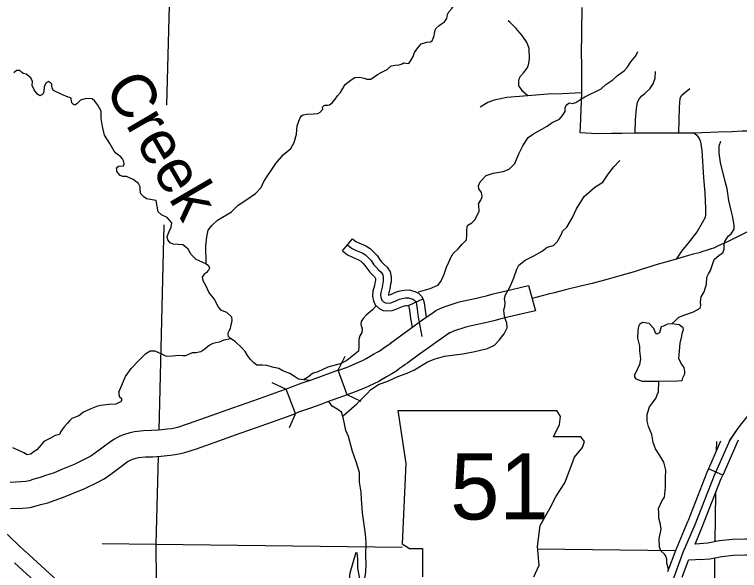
# Model space of a CAD drawing. Extents: x 813775 to 1157140, y 1757555 to 1979907.
# Drawn here: x 951173 to 965049, y 1822306 to 1832939 of the extents above; entities that cross this region are included whole.
import ezdxf

# ---------------------------------------------------------------- set-up
doc = ezdxf.new("R2010")
doc.units = 0
for name, color, linetype in [('Level 10', 7, 'Continuous'), ('Level 21', 7, 'Continuous'), ('Level 31', 7, 'Continuous'), ('Level 32', 7, 'Continuous'), ('Level 35', 7, 'Continuous'), ('Level 37', 7, 'Continuous'), ('Level 45', 7, 'Continuous'), ('Level 5', 7, 'Continuous')]:
    doc.layers.add(name, color=color, linetype=linetype)

msp = doc.modelspace()

# ---------------------------------------------------------------- linework, layer by layer
at = {"layer": 'Level 10'}
msp.add_line((958386, 1826665), (958378, 1826659), dxfattribs=at)
for points in [[(965811, 1829193), (965710, 1829119), (965609, 1829037), (965530, 1828986), (965404, 1828901), (965305, 1828839), (965153, 1828760), (964848, 1828606)], [(964848, 1828606), (964700, 1828538), (964630, 1828506), (964569, 1828479), (964485, 1828450), (964413, 1828426), (964348, 1828405), (964276, 1828380), (964163, 1828353), (964073, 1828328)], [(964073, 1828328), (963835, 1828263), (963727, 1828227), (963613, 1828194), (963517, 1828168), (963412, 1828138), (963315, 1828108), (963187, 1828068)], [(963187, 1828068), (963034, 1828021), (962806, 1827951), (962538, 1827878), (962232, 1827796)], [(962232, 1827796), (962009, 1827743), (961722, 1827676), (961499, 1827617), (961370, 1827584), (961080, 1827505)], [(960041, 1827522), (960223, 1827566), (960336, 1827598), (960499, 1827635), (960691, 1827682), (961011, 1827757), (961143, 1827275)], [(959237, 1827276), (959322, 1827316), (959398, 1827347), (959493, 1827381), (959587, 1827410), (959664, 1827435), (959743, 1827458), (960046, 1827523)], [(958378, 1826659), (958628, 1826845), (958824, 1826985), (958964, 1827087), (959055, 1827151), (959160, 1827221), (959237, 1827276)], [(961143, 1827275), (960809, 1827196), (960614, 1827148), (960459, 1827113), (960350, 1827082), (960158, 1827036)], [(960152, 1827035), (959865, 1826972), (959811, 1826957), (959737, 1826933), (959650, 1826906), (959575, 1826880), (959523, 1826859), (959472, 1826834)], [(959511, 1826857), (959445, 1826810), (959337, 1826738), (959254, 1826680), (959117, 1826580), (958922, 1826441), (958675, 1826257)], [(957416, 1826151), (957559, 1826204), (957686, 1826257), (957832, 1826323), (957902, 1826360), (957981, 1826405), (958047, 1826444), (958137, 1826495), (958201, 1826535), (958248, 1826572), (958335, 1826631), (958386, 1826665)], [(957371, 1826135), (957401, 1826146), (957559, 1826204), (957686, 1826257), (957832, 1826323), (957882, 1826349)], [(958666, 1826251), (958616, 1826217), (958542, 1826167), (958490, 1826126), (958395, 1826066), (958296, 1826010), (958231, 1825972), (958143, 1825921), (958051, 1825873), (957885, 1825799), (957742, 1825739), (957588, 1825682)], [(957371, 1826135), (957214, 1826079), (957042, 1826017), (956852, 1825945), (956675, 1825886), (956434, 1825800), (956372, 1825777)], [(957539, 1825664), (957371, 1826135)], [(958218, 1825965), (958143, 1825921), (958051, 1825873), (957885, 1825799), (957742, 1825739), (957539, 1825664)], [(956372, 1825777), (956227, 1825721), (955944, 1825620), (955510, 1825469), (955326, 1825404), (954844, 1825232), (954499, 1825108), (954292, 1825043), (954240, 1825029), (954176, 1825017), (954100, 1825009), (953933, 1824990), (953797, 1824982), (953645, 1824978), (953470, 1824959), (953379, 1824941), (953257, 1824903), (953192, 1824874), (953074, 1824814)], [(956550, 1825309), (956372, 1825777)], [(957539, 1825664), (957383, 1825609), (957215, 1825548), (957020, 1825474), (956838, 1825413), (956606, 1825331), (956549, 1825309)], [(953330, 1824383), (953406, 1824422), (953434, 1824434), (953504, 1824456), (953547, 1824465), (953679, 1824479), (953818, 1824483), (953974, 1824492), (954156, 1824512), (954250, 1824522), (954350, 1824541), (954432, 1824562), (954659, 1824634), (955013, 1824761), (955494, 1824933), (955675, 1824997), (956110, 1825148), (956400, 1825252), (956549, 1825309)], [(953074, 1824814), (952994, 1824756), (952872, 1824665), (952725, 1824555), (952633, 1824490)], [(952633, 1824490), (952532, 1824439), (952314, 1824331), (952092, 1824241), (951935, 1824175), (951767, 1824120), (951663, 1824082), (951542, 1824050), (951451, 1824023), (951391, 1824007), (951297, 1823999), (951091, 1823991)], [(952891, 1824061), (953018, 1824150), (953172, 1824264), (953330, 1824383)], [(951096, 1823491), (951329, 1823500), (951476, 1823513), (951586, 1823541), (951676, 1823569), (951812, 1823603), (951932, 1823648), (952110, 1823707), (952282, 1823778), (952519, 1823875), (952756, 1823992), (952891, 1824061)]]:
    msp.add_lwpolyline(points, dxfattribs=at)
at = {"layer": 'Level 21'}
for p, q in [((958510, 1825367), (958662, 1824352)), ((961623, 1825249), (961553, 1825366)), ((961606, 1825097), (961623, 1825249)), ((961488, 1824860), (961606, 1825097)), ((962012, 1824860), (961488, 1824860)), ((962080, 1824775), (962012, 1824860)), ((962046, 1824657), (962080, 1824775)), ((961894, 1824471), (962046, 1824657)), ((961809, 1824251), (961894, 1824471)), ((958662, 1824352), (958595, 1822813)), ((961707, 1823980), (961809, 1824251)), ((961538, 1823726), (961707, 1823980)), ((961420, 1823489), (961538, 1823726)), ((961234, 1823168), (961420, 1823489)), ((961183, 1822762), (961234, 1823168)), ((958595, 1822813), (958730, 1822728)), ((958730, 1822728), (958984, 1822728)), ((958984, 1822728), (958984, 1822187)), ((961217, 1822407), (961183, 1822762)), ((961115, 1822187), (961217, 1822407))]:
    msp.add_line(p, q, dxfattribs=at)
msp.add_lwpolyline([(958510, 1825367), (961553, 1825366)], dxfattribs=at)
at = {"layer": 'Level 31'}
for p, q in [((964730, 1824131), (964455, 1824252)), ((964343, 1823155), (964343, 1823155))]:
    msp.add_line(p, q, dxfattribs=at)
for points in [[(962033, 1833075), (962021, 1832151), (962022, 1832019)], [(962022, 1832019), (962026, 1831438), (962009, 1830963)], [(962026, 1831438), (961904, 1831434), (961656, 1831423), (961382, 1831416), (961001, 1831383), (960594, 1831354), (960355, 1831303), (960230, 1831258), (960088, 1831165)], [(962009, 1830963), (962008, 1830938), (961995, 1830680), (962332, 1830663), (962600, 1830667), (962797, 1830670)], [(963853, 1830676), (963889, 1830676), (964172, 1830678), (964644, 1830696), (964908, 1830701)], [(964908, 1830701), (964913, 1830701), (965103, 1830712), (965587, 1830712), (965854, 1830716), (965964, 1830717)], [(962797, 1830670), (963053, 1830674), (963853, 1830676)], [(964172, 1830678), (964223, 1830638), (964279, 1830570), (964305, 1830501), (964327, 1830341), (964363, 1829818), (964387, 1829531), (964401, 1829229), (964401, 1829113), (964392, 1829058), (964332, 1828953), (964241, 1828789), (964088, 1828589), (963941, 1828412), (963835, 1828263)], [(965088, 1825118), (965016, 1825026), (964852, 1824786)], [(964688, 1824779), (964455, 1824252)], [(965026, 1824801), (964730, 1824131)], [(964455, 1824252), (964424, 1824181), (964064, 1823265)], [(964343, 1823155), (964701, 1824065), (964730, 1824131)], [(950610, 1823396), (950746, 1823267), (950977, 1823054), (951365, 1822681), (951374, 1822673)], [(964064, 1823265), (964054, 1823238), (963828, 1822704), (963670, 1822282)], [(964198, 1822808), (964331, 1823125), (964343, 1823155)], [(965321, 1822908), (965162, 1822905), (964917, 1822902), (964660, 1822871), (964443, 1822826), (964198, 1822808)], [(951374, 1822673), (951604, 1822465), (951992, 1822113), (952159, 1821982)], [(963951, 1822177), (964073, 1822502)], [(964286, 1822514), (964209, 1822508), (964073, 1822502)], [(964286, 1822514), (964484, 1822528), (964708, 1822575), (964937, 1822602), (965167, 1822605), (965327, 1822608)], [(951973, 1821746), (951799, 1821883), (951402, 1822243), (951173, 1822450)]]:
    msp.add_lwpolyline(points, dxfattribs=at)
at = {"layer": 'Level 32'}
for points in [[(963053, 1830674), (963060, 1830923), (963077, 1831143), (963097, 1831263), (963135, 1831332), (963177, 1831383), (963236, 1831430), (963271, 1831459), (963333, 1831518), (963395, 1831614), (963433, 1831723), (963442, 1831847)], [(963889, 1830676), (963900, 1831163), (963916, 1831341), (963947, 1831396), (963998, 1831443), (964098, 1831523)]]:
    msp.add_lwpolyline(points, dxfattribs=at)
at = {"layer": 'Level 35'}
for points in [[(959200, 1832508), (959216, 1832607), (959226, 1832639), (959245, 1832678), (959303, 1832727), (959346, 1832762), (959406, 1832800), (959449, 1832860), (959463, 1832939), (959485, 1832993), (959542, 1833056), (959604, 1833148), (959634, 1833213), (959691, 1833260), (959762, 1833292), (959797, 1833314), (959849, 1833371), (959903, 1833456), (959985, 1833608), (960009, 1833679), (960050, 1833738), (960126, 1833842), (960178, 1833923), (960218, 1833986)], [(956584, 1830807), (956632, 1830947), (956665, 1831001), (956697, 1831023), (956768, 1831034), (956898, 1831037), (956977, 1831047), (957023, 1831072), (957072, 1831129), (957070, 1831164), (957102, 1831200), (957121, 1831208), (957173, 1831205), (957203, 1831211), (957254, 1831249), (957309, 1831317), (957355, 1831382), (957415, 1831447), (957456, 1831523), (957502, 1831600), (957619, 1831687), (957689, 1831733), (957776, 1831738), (957863, 1831719), (957915, 1831700), (957996, 1831700), (958056, 1831744), (958119, 1831793), (958192, 1831828), (958306, 1831888), (958385, 1831956), (958461, 1831972), (958534, 1831975), (958594, 1831997), (958616, 1832016), (958660, 1832008), (958719, 1832005), (958757, 1832059), (958804, 1832138), (958831, 1832212), (958891, 1832301), (958956, 1832375), (959064, 1832413), (959132, 1832418), (959170, 1832435), (959189, 1832484), (959200, 1832508)], [(960823, 1830272), (960902, 1830429), (961005, 1830584), (961108, 1830658), (961367, 1830805), (961462, 1830873), (961606, 1830935), (961660, 1831006), (961712, 1831082), (961714, 1831153), (961731, 1831207), (961782, 1831245), (961796, 1831251), (961850, 1831240), (961916, 1831256), (961992, 1831308), (962092, 1831365), (962399, 1831515), (962492, 1831599), (962625, 1831689), (962712, 1831770), (962840, 1831860), (962899, 1831925), (962967, 1832037), (963068, 1832151), (963106, 1832233)], [(951398, 1831796), (951342, 1831811), (951307, 1831838), (951277, 1831868), (951239, 1831870), (951211, 1831865), (951162, 1831821)], [(953883, 1829385), (953697, 1829417), (953648, 1829450), (953594, 1829512), (953578, 1829580), (953575, 1829646), (953548, 1829706), (953447, 1829782), (953317, 1829842), (953249, 1829844), (953194, 1829861), (953129, 1829934), (953129, 1829978), (953126, 1830008), (953164, 1830040), (953257, 1830048), (953270, 1830086), (953257, 1830138), (953243, 1830182), (953200, 1830225), (953162, 1830250), (953115, 1830288), (953083, 1830323), (952996, 1830473), (952895, 1830633), (952855, 1830795), (952833, 1830947), (952830, 1831088), (952770, 1831205), (952713, 1831279), (952659, 1831325), (952545, 1831330), (952501, 1831319), (952439, 1831298), (952368, 1831230), (952327, 1831205), (952300, 1831216), (952268, 1831251), (952259, 1831325), (952249, 1831344), (952200, 1831360), (952077, 1831407), (951920, 1831485), (951892, 1831529), (951890, 1831578), (951890, 1831608), (951865, 1831635), (951825, 1831657), (951781, 1831635), (951743, 1831559), (951732, 1831453), (951710, 1831412), (951656, 1831385), (951610, 1831417), (951555, 1831488), (951509, 1831581), (951515, 1831660), (951488, 1831728), (951398, 1831796)], [(956057, 1829917), (956174, 1830089), (956318, 1830255), (956464, 1830374), (956527, 1830494), (956573, 1830652), (956584, 1830807)], [(964893, 1829168), (964842, 1829383), (964815, 1829604), (964777, 1829748), (964687, 1830107), (964657, 1830286), (964657, 1830425), (964690, 1830515)], [(959513, 1828267), (959570, 1828368), (959663, 1828460), (959744, 1828545), (959823, 1828632), (959831, 1828716), (959828, 1828806), (959836, 1828887), (959850, 1828909), (959929, 1828953), (959991, 1829018), (960067, 1829176), (960057, 1829290), (960051, 1829317), (960100, 1829388), (960125, 1829456), (960111, 1829535), (960059, 1829603), (960051, 1829665), (960084, 1829736), (960203, 1829858), (960337, 1829905), (960527, 1829937), (960641, 1829983), (960750, 1830092), (960823, 1830272)], [(961662, 1828794), (961744, 1828874), (961852, 1829059), (961931, 1829225), (962073, 1829458), (962282, 1829635), (962431, 1829733), (962535, 1829883), (962646, 1830027), (962760, 1830149)], [(954843, 1828172), (954843, 1828312), (954832, 1828385), (954832, 1828516), (954851, 1828684), (954881, 1828815), (954951, 1828907), (955057, 1829005), (955329, 1829163), (955454, 1829291), (955598, 1829386), (955783, 1829519), (955897, 1829631), (955943, 1829745), (956030, 1829873), (956057, 1829917)], [(954557, 1828352), (954500, 1828450), (954454, 1828491), (954394, 1828531), (954304, 1828542), (954209, 1828548), (954155, 1828572), (954106, 1828632), (954095, 1828695), (954136, 1828787), (954174, 1828869), (954182, 1828956), (954095, 1829056), (953989, 1829105), (953924, 1829168), (953883, 1829385)], [(964495, 1828043), (964567, 1828251), (964660, 1828335), (964733, 1828384), (964755, 1828452), (964758, 1828531), (964766, 1828599), (964831, 1828700), (964891, 1828746), (964945, 1828833), (964948, 1828912), (964918, 1829089), (964893, 1829168)], [(959402, 1826402), (959753, 1826451), (959981, 1826492), (960226, 1826552), (960362, 1826614), (960452, 1826710), (960544, 1826832), (960601, 1826949), (960598, 1827041), (960579, 1827090), (960558, 1827147), (960544, 1827215), (960536, 1827294), (960560, 1827357), (960563, 1827426), (960552, 1827505), (960571, 1827578), (960620, 1827665), (960669, 1827752), (960729, 1827904), (960787, 1828070), (960825, 1828144), (960950, 1828239), (961113, 1828326), (961271, 1828416), (961371, 1828489), (961488, 1828522), (961562, 1828593), (961641, 1828740), (961662, 1828794)], [(954557, 1828352), (954644, 1828259), (954758, 1828210), (954843, 1828172), (954889, 1828136), (954905, 1828090), (954889, 1828047), (954843, 1828000), (954802, 1827976), (954766, 1827916), (954780, 1827853), (954826, 1827766), (954900, 1827611), (954997, 1827492), (955079, 1827337), (955117, 1827290), (955228, 1827247), (955332, 1827154)], [(959513, 1828267), (959438, 1828098), (959389, 1827964), (959340, 1827850), (959269, 1827758), (959125, 1827690), (958901, 1827629)], [(963755, 1827021), (963823, 1827088), (963891, 1827151), (964005, 1827197), (964171, 1827251), (964296, 1827322), (964310, 1827371), (964302, 1827444), (964315, 1827537), (964372, 1827635), (964416, 1827779), (964427, 1827918), (964454, 1827980), (964495, 1828043)], [(958098, 1827368), (958024, 1827294), (957905, 1827190), (957848, 1827125), (957810, 1827071), (957804, 1827014), (957826, 1826929), (957820, 1826859), (957782, 1826791), (957766, 1826725), (957766, 1826671), (957761, 1826595), (957759, 1826499)], [(955310, 1826743), (955270, 1826784), (955265, 1826817), (955262, 1826852), (955284, 1826890), (955308, 1826931), (955311, 1826972), (955333, 1827054), (955338, 1827084), (955332, 1827154)], [(963951, 1826839), (963975, 1826913), (963970, 1826948), (963897, 1827002), (963755, 1827021), (963674, 1827016), (963592, 1826981), (963551, 1826967), (963538, 1826921), (963519, 1826853), (963465, 1826826), (963437, 1826861), (963407, 1826934), (963318, 1827030), (963195, 1827051), (963138, 1827013), (963114, 1826972), (963103, 1826899), (963098, 1826747), (963138, 1826594), (963138, 1826507), (963157, 1826355), (963138, 1826243)], [(963138, 1826243), (963065, 1826094), (963041, 1826045), (963038, 1826010), (963062, 1825969), (963185, 1825928), (963508, 1825928), (963861, 1825931), (963954, 1825939), (963967, 1825988), (964003, 1826064), (964005, 1826113), (963992, 1826189), (963935, 1826263), (963888, 1826363), (963899, 1826505), (963916, 1826651), (963943, 1826785), (963951, 1826839)], [(953172, 1825718), (953297, 1826015), (953403, 1826170), (953547, 1826317), (953686, 1826458), (953767, 1826510), (953857, 1826510), (953987, 1826450), (954077, 1826404), (954188, 1826409), (954319, 1826423), (954392, 1826420), (954452, 1826420), (954534, 1826453), (954577, 1826472), (954642, 1826474), (954740, 1826496), (954816, 1826548), (954868, 1826591), (954914, 1826621), (954974, 1826654), (955028, 1826665), (955096, 1826676), (955183, 1826716), (955310, 1826743)], [(956611, 1825966), (956530, 1826014), (956443, 1826074), (956308, 1826126), (956234, 1826172), (956139, 1826188), (956000, 1826224), (955913, 1826232), (955813, 1826232), (955756, 1826278), (955691, 1826343), (955631, 1826417), (955587, 1826493), (955530, 1826561), (955394, 1826686), (955310, 1826743)], [(957759, 1826499), (957533, 1826320), (957403, 1826258), (957167, 1826195), (956977, 1826105), (956876, 1826071), (956801, 1826011), (956707, 1825955)], [(957468, 1825268), (957727, 1825494), (957931, 1825695), (957987, 1825761), (958138, 1825864), (958328, 1825935), (958512, 1826014), (958686, 1826077), (958830, 1826146), (959075, 1826297), (959224, 1826352), (959402, 1826402)], [(956837, 1825939), (956709, 1825955), (956611, 1825966)], [(963397, 1824757), (963372, 1824905), (963307, 1825062), (963285, 1825160), (963282, 1825291), (963326, 1825435), (963445, 1825593), (963472, 1825664), (963497, 1825726), (963508, 1825928)], [(953172, 1825718), (953170, 1825674), (953181, 1825630), (953219, 1825600), (953222, 1825559), (953200, 1825529), (953110, 1825486), (952977, 1825480), (952825, 1825459), (952762, 1825450), (952637, 1825396), (952496, 1825331), (952406, 1825266), (952273, 1825211), (952233, 1825173), (952186, 1825121), (952121, 1825053), (952061, 1824966), (952034, 1824904), (951953, 1824885), (951863, 1824838), (951732, 1824770), (951686, 1824708), (951599, 1824615), (951531, 1824569), (951488, 1824528), (951417, 1824517), (951349, 1824556), (951243, 1824607), (951140, 1824653)], [(957370, 1825381), (957364, 1825383), (957250, 1825446), (957192, 1825539)], [(957514, 1824982), (957487, 1825111), (957465, 1825234), (957432, 1825337), (957370, 1825381)], [(957805, 1823805), (957775, 1823997), (957777, 1824180), (957707, 1824405), (957644, 1824579), (957568, 1824870), (957514, 1824982)], [(963498, 1823494), (963568, 1823642), (963612, 1823710), (963631, 1823900), (963634, 1824074), (963642, 1824227), (963604, 1824379), (963522, 1824504), (963441, 1824635), (963397, 1824757)], [(957884, 1821983), (957870, 1822115), (957897, 1822273), (957902, 1822434), (957900, 1822581), (957905, 1822847), (957891, 1823000), (957834, 1823408), (957815, 1823669), (957805, 1823805)], [(963688, 1822330), (963661, 1822449), (963661, 1822525), (963631, 1822596), (963614, 1822621), (963541, 1822680), (963517, 1822759), (963514, 1822914), (963549, 1823099), (963538, 1823186), (963506, 1823306), (963503, 1823415), (963498, 1823494)], [(957612, 1820994), (957636, 1821124), (957639, 1821274), (957655, 1821523), (957647, 1821721), (957615, 1821893), (957587, 1822143), (957596, 1822260), (957653, 1822458), (957712, 1822654)], [(957723, 1822652), (957737, 1822524), (957737, 1822352), (957778, 1822148), (957821, 1821928), (957881, 1821561), (957973, 1821302), (958074, 1821185), (958204, 1821000)]]:
    msp.add_lwpolyline(points, dxfattribs=at)
at = {"layer": 'Level 37'}
for points in [[(957371, 1826135), (957499, 1826406)], [(956098, 1825900), (956372, 1825777)], [(957810, 1825536), (957539, 1825664)], [(956549, 1825309), (956427, 1825036)]]:
    msp.add_lwpolyline(points, dxfattribs=at)
at = {"layer": 'Level 45'}
for p, q in [((957451, 1828417), (957643, 1828648)), ((958715, 1827376), (958987, 1827503))]:
    msp.add_line(p, q, dxfattribs=at)
for points in [[(961001, 1831383), (960898, 1831470), (960861, 1831522), (960827, 1831573), (960823, 1831610), (960823, 1831655), (960834, 1831708), (960856, 1831757), (960918, 1831826), (960983, 1831915), (961012, 1831977), (961025, 1832048), (961029, 1832104), (961027, 1832155), (961023, 1832228), (961021, 1832290), (960998, 1832359), (960978, 1832406), (960961, 1832437), (960927, 1832479), (960890, 1832535), (960852, 1832579), (960805, 1832630), (960774, 1832670), (960728, 1832719), (960690, 1832755), (960659, 1832786), (960621, 1832815)], [(957643, 1828648), (957705, 1828597), (957761, 1828572), (957895, 1828513), (957983, 1828462), (958060, 1828387), (958116, 1828329), (958174, 1828240), (958198, 1828212), (958243, 1828167), (958307, 1828105), (958362, 1828015), (958381, 1827922), (958381, 1827828), (958372, 1827780)], [(957547, 1828533), (957625, 1828468), (957700, 1828435), (957827, 1828379), (957891, 1828342), (957954, 1828282), (957998, 1828235), (958053, 1828151), (958087, 1828111), (958138, 1828059), (958189, 1828011), (958220, 1827959), (958231, 1827906), (958231, 1827842), (958209, 1827725)], [(957451, 1828417), (957545, 1828340), (957640, 1828298), (957759, 1828246), (957800, 1828221), (957847, 1828176), (957880, 1828141), (957933, 1828061), (957976, 1828009), (958033, 1827952), (958071, 1827916), (958078, 1827904), (958081, 1827891), (958081, 1827856), (958077, 1827836)], [(958077, 1827836), (958062, 1827757), (958034, 1827648), (958023, 1827553), (958046, 1827463), (958075, 1827389), (958150, 1827319), (958232, 1827276), (958312, 1827269), (958404, 1827281), (958480, 1827303), (958534, 1827327), (958596, 1827354), (958630, 1827365), (958663, 1827371), (958691, 1827372), (958712, 1827365), (958722, 1827362), (958715, 1827376)], [(958372, 1827780), (958355, 1827692), (958330, 1827593), (958328, 1827574), (958342, 1827576), (958377, 1827585), (958412, 1827601), (958487, 1827634), (958556, 1827657), (958634, 1827670), (958735, 1827673), (958793, 1827654), (958835, 1827644), (958905, 1827607), (958969, 1827543), (958987, 1827503)], [(958209, 1827725), (958182, 1827620), (958176, 1827563), (958189, 1827509), (958202, 1827476), (958238, 1827443), (958275, 1827423), (958309, 1827419), (958373, 1827428), (958429, 1827444), (958473, 1827464), (958542, 1827494), (958593, 1827511), (958648, 1827520), (958713, 1827523), (958753, 1827509), (958782, 1827503), (958815, 1827485), (958844, 1827456), (958859, 1827423), (958864, 1827400), (958879, 1827305), (958899, 1827151), (958933, 1826983), (958970, 1826783)], [(958987, 1827503), (959003, 1827470), (959011, 1827427), (959028, 1827327), (959051, 1827148)], [(958715, 1827376), (958716, 1827376), (958716, 1827374), (958731, 1827283), (958751, 1827127), (958785, 1826957)]]:
    msp.add_lwpolyline(points, dxfattribs=at)
at = {"layer": 'Level 5'}
for points in [[(954137, 1833359), (954084, 1831203)], [(954029, 1828918), (953934, 1824990)], [(966790, 1826157), (966307, 1825902), (966127, 1825851), (965529, 1825662), (965231, 1825305), (965016, 1825026), (964861, 1824799), (964562, 1824123), (964193, 1823182), (963967, 1822648)], [(964606, 1824776), (964603, 1824587)], [(953922, 1824486), (953881, 1822808)], [(964590, 1823783), (964574, 1822853)], [(952851, 1822822), (953881, 1822808)], [(953881, 1822808), (958592, 1822753)], [(953881, 1822808), (953892, 1821362)], [(961178, 1822722), (963822, 1822691)], [(963967, 1822648), (963719, 1821984), (963466, 1821399), (963330, 1821126), (963142, 1820834), (962921, 1820549), (962616, 1820185), (962240, 1819821), (961841, 1819446)], [(964571, 1822546), (964571, 1818353), (964533, 1812091)]]:
    msp.add_lwpolyline(points, dxfattribs=at)

# ---------------------------------------------------------------- texts
at = {"layer": 'Level 21'}
msp.add_text('51', height=1267.2, dxfattribs=at).set_placement((959511, 1823282))
at = {"layer": 'Level 35'}
msp.add_text('Creek', height=844.8, rotation=300.2316, dxfattribs=at).set_placement((952880, 1831542))

doc.saveas('drawing.dxf')
